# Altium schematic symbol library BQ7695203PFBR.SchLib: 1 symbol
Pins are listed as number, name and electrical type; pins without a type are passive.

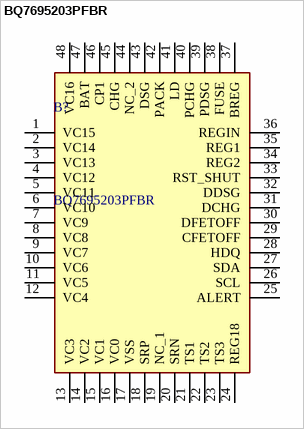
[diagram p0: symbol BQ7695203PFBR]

## BQ7695203PFBR
designator B?
Battery Management 3-s to 16-s high-accuracy battery monitor and protector for Li-ion, Li-polymer and LiFePO4; Manufacturer_Name: Texas Instruments; Geometry.Height: 1.2mm
footprint QFP50P900X900X120-48N
pins: 1 VC15, 2 VC14, 3 VC13, 4 VC12, 5 VC11, 6 VC10, 7 VC9, 8 VC8, 9 VC7, 10 VC6, 11 VC5, 12 VC4, 13 VC3, 14 VC2, 15 VC1, 16 VC0, 17 VSS, 18 SRP, 19 NC_1, 20 SRN, 21 TS1, 22 TS2, 23 TS3, 24 REG18, 25 ALERT, 26 SCL, 27 SDA, 28 HDQ, 29 CFETOFF, 30 DFETOFF, 31 DCHG, 32 DDSG, 33 RST_SHUT, 34 REG2, 35 REG1, 36 REGIN, 37 BREG, 38 FUSE, 39 PDSG, 40 PCHG, 41 LD, 42 PACK, 43 DSG, 44 NC_2, 45 CHG, 46 CP1, 47 BAT, 48 VC16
